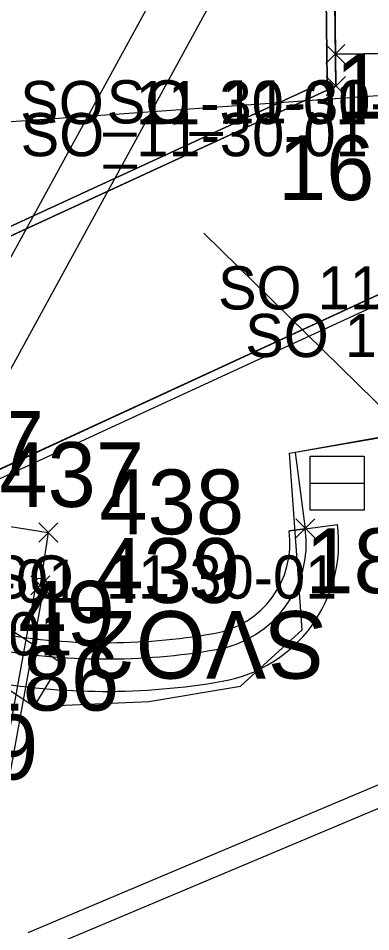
# Model space of a CAD drawing. Extents: x -728800 to -728100, y -1073200 to -1072700.
# Drawn here: x -728515.29 to -728512.03, y -1073056.81 to -1073048.35 of the extents above; entities that cross this region are included whole.
import ezdxf

# ---------------------------------------------------------------- set-up
doc = ezdxf.new("R2010")
doc.units = 0
for name, color, linetype in [('_NOR-návrh tenká', 7, 'Continuous'), ('_NOR-šraf_+-0', 7, 'Continuous'), ('_NOR-šraf_+12', 7, 'Continuous'), ('_NOR-šraf_+6', 7, 'Continuous'), ('_NOR-šraf_chodník', 7, 'Continuous'), ('_NOR-šraf_signální pás', 7, 'Continuous'), ('_NOR-šraf_vozovka', 7, 'Continuous'), ('_NOR-šraf_zeleň', 7, 'Continuous'), ('A2_OBVOD STAVBY', 7, 'Continuous'), ('B1_body_poloha', 7, 'Continuous'), ('B2_body_číslo', 7, 'Continuous'), ('B3_body_popiska', 7, 'Continuous'), ('B4_Bodové pole', 7, 'Continuous'), ('B6_JŽM', 7, 'Continuous'), ('KOS_kabelová trasa VO', 7, 'Continuous'), ('KOS_nové prvky VO', 7, 'Continuous'), ('KTA_členění PS a SO', 7, 'Continuous'), ('ZA_02_Dočasný_do_1_roku', 7, 'Continuous')]:
    doc.layers.add(name, color=color, linetype=linetype)

msp = doc.modelspace()

# ---------------------------------------------------------------- linework, layer by layer
at = {"layer": '_NOR-návrh tenká'}
msp.add_line((-728511.5598, -1073048.6726), (-728512.3598, -1073048.6815), dxfattribs=at)
for points in [[(-728512.437, -1073048.9275), (-728512.4624, -1073046.6351)], [(-728512.3565, -1073048.9785), (-728512.3823, -1073046.6472)], [(-728516.9231, -1073050.9957), (-728512.437, -1073048.9275)], [(-728516.8896, -1073051.0683), (-728512.3565, -1073048.9785)], [(-728516.0858, -1073052.812), (-728510.6464, -1073050.3043)], [(-728516.0523, -1073052.8846), (-728510.6571, -1073050.3973)], [(-728512.6386, -1073053.0791), (-728512.3411, -1073053.0398)], [(-728512.6386, -1073053.0791), (-728512.7873, -1073053.0987)], [(-728512.6386, -1073053.0791), (-728512.6386, -1073053.0791)]]:
    msp.add_lwpolyline(points, dxfattribs=at)
for centre, radius, start, end in [((-728513.6299, -1073053.2101), 1.3, 279.85546, 7.52816), ((-728513.6299, -1073053.2101), 0.85, 279.85546, 7.52816), ((-728513.6299, -1073053.2101), 1, 279.85546, 7.52816), ((-728514.4858, -1073048.2839), 5.85, 259.67159, 279.85546), ((-728514.4858, -1073048.2839), 6, 259.67159, 279.85546), ((-728514.4858, -1073048.2839), 6.3, 259.67159, 279.85546)]:
    msp.add_arc(centre, radius, start, end, dxfattribs=at)
at = {"layer": '_NOR-šraf_+-0'}
msp.add_lwpolyline([(-728516.0523, -1073052.8846), (-728510.6571, -1073050.3973), (-728510.6464, -1073050.3043), (-728516.0858, -1073052.812)], dxfattribs=at)
at = {"layer": '_NOR-šraf_+12'}
msp.add_lwpolyline([(-728512.7873, -1073053.0987), (-728512.6386, -1073053.0791)], dxfattribs=at)
for centre, radius, start, end in [((-728513.6299, -1073053.2101), 0.85, 279.85546, 7.52816), ((-728513.6299, -1073053.2101), 1, 279.85546, 7.52816), ((-728514.4858, -1073048.2839), 5.85, 259.67159, 279.85546), ((-728514.4858, -1073048.2839), 6, 259.67159, 279.85546)]:
    msp.add_arc(centre, radius, start, end, dxfattribs=at)
at = {"layer": '_NOR-šraf_+6'}
for points in [[(-728516.9231, -1073050.9957), (-728512.437, -1073048.9275), (-728512.4624, -1073046.6351)], [(-728512.4624, -1073046.6351), (-728512.3823, -1073046.6472), (-728512.3823, -1073046.6472), (-728512.3778, -1073047.0523), (-728512.3598, -1073048.6815), (-728512.3565, -1073048.9785), (-728516.7519, -1073051.0049), (-728516.8896, -1073051.0683)]]:
    msp.add_lwpolyline(points, dxfattribs=at)
at = {"layer": '_NOR-šraf_chodník'}
for p, q in [((-728512.3598, -1073048.6815), (-728511.5598, -1073048.6726)), ((-728512.3565, -1073048.9785), (-728512.3598, -1073048.6815)), ((-728516.7519, -1073051.0049), (-728512.3565, -1073048.9785)), ((-728510.6464, -1073050.3043), (-728516.0858, -1073052.812))]:
    msp.add_line(p, q, dxfattribs=at)
at = {"layer": '_NOR-šraf_signální pás'}
msp.add_lwpolyline([(-728512.3598, -1073048.6815), (-728511.5598, -1073048.6726), (-728511.5764, -1073047.1727), (-728512.3778, -1073047.0523), (-728512.3598, -1073048.6815)], dxfattribs=at)
at = {"layer": '_NOR-šraf_vozovka'}
msp.add_lwpolyline([(-728512.6386, -1073053.0791), (-728512.3411, -1073053.0398)], dxfattribs=at)
for centre, radius, start, end in [((-728513.6299, -1073053.2101), 1.3, 279.85546, 7.52816), ((-728513.6299, -1073053.2101), 1, 279.85546, 7.52816), ((-728514.4858, -1073048.2839), 6, 259.67159, 279.85546), ((-728514.4858, -1073048.2839), 6.3, 259.67159, 279.85546)]:
    msp.add_arc(centre, radius, start, end, dxfattribs=at)
at = {"layer": '_NOR-šraf_zeleň'}
for points in [[(-728515.0597, -1073046.2449), (-728512.4624, -1073046.6351), (-728512.437, -1073048.9275), (-728516.9231, -1073050.9957)], [(-728516.0523, -1073052.8846), (-728510.6571, -1073050.3973), (-728510.7036, -1073050.8035), (-728510.5546, -1073050.8206), (-728510.651, -1073051.661), (-728511.32, -1073052.432), (-728511.438, -1073052.141), (-728512.732, -1073052.372), (-728512.6386, -1073053.0791), (-728512.7873, -1073053.0987)]]:
    msp.add_lwpolyline(points, dxfattribs=at)
for centre, radius, start, end in [((-728513.6299, -1073053.2101), 0.85, 279.85546, 7.52816), ((-728514.4858, -1073048.2839), 5.85, 259.67159, 279.85546)]:
    msp.add_arc(centre, radius, start, end, dxfattribs=at)
at = {"layer": 'A2_OBVOD STAVBY'}
msp.add_lwpolyline([(-728515.0412, -1073056.9667), (-728511.7977, -1073055.5968), (-728511.0404, -1073055.2769), (-728508.4004, -1073049.5903), (-728508.3173, -1073048.8652)], dxfattribs=at)
at = {"layer": 'B1_body_poloha'}
for p, q in [((-728512.4484, -1073048.5926), (-728512.2716, -1073048.7694)), ((-728512.4484, -1073048.7694), (-728512.2716, -1073048.5926)), ((-728512.4444, -1073048.8896), (-728512.2676, -1073049.0664)), ((-728512.4444, -1073049.0664), (-728512.2676, -1073048.8896)), ((-728515.1044, -1073053.0246), (-728514.9276, -1073053.2014)), ((-728515.1044, -1073053.2014), (-728514.9276, -1073053.0246)), ((-728512.7264, -1073052.9866), (-728512.5496, -1073053.1634)), ((-728512.7264, -1073053.1634), (-728512.5496, -1073052.9866)), ((-728515.1784, -1073053.5126), (-728515.0016, -1073053.6894)), ((-728515.1784, -1073053.6894), (-728515.0016, -1073053.5126))]:
    msp.add_line(p, q, dxfattribs=at)
at = {"layer": 'B2_body_číslo'}
for p, q in [((-728512.36, -1073048.681), (-728512.36, -1073048.681)), ((-728512.356, -1073048.978), (-728512.356, -1073048.978)), ((-728515.016, -1073053.113), (-728515.016, -1073053.113)), ((-728512.638, -1073053.075), (-728512.638, -1073053.075)), ((-728515.09, -1073053.601), (-728515.09, -1073053.601))]:
    msp.add_line(p, q, dxfattribs=at)
at = {"layer": 'B4_Bodové pole'}
msp.add_line((-728502.086, -1073048.369), (-728521.333, -1073049.732), dxfattribs=at)
at = {"layer": 'B6_JŽM'}
for points in [[(-728515.148, -1073054.725), (-728514.9, -1073054.321), (-728516.336, -1073053.379), (-728512.168, -1073045.742), (-728510.38, -1073046.047), (-728509.916, -1073045.565), (-728514.343, -1073044.959), (-728514.586, -1073045.376), (-728512.695, -1073045.676), (-728516.744, -1073053.086), (-728518.227, -1073052.067), (-728518.483, -1073052.487), (-728515.148, -1073054.725)], [(-728515.148, -1073054.725), (-728514.0859, -1073054.6787), (-728513.2393, -1073054.5358), (-728512.667, -1073054.014), (-728512.785, -1073052.379), (-728511.438, -1073052.146), (-728511.426, -1073052.561), (-728510.655, -1073051.729), (-728509.916, -1073045.565)], [(-728512.594, -1073052.656), (-728512.594, -1073052.406), (-728512.094, -1073052.406), (-728512.094, -1073052.906), (-728512.594, -1073052.906), (-728512.594, -1073052.656), (-728512.094, -1073052.656)]]:
    msp.add_lwpolyline(points, dxfattribs=at)
at = {"layer": 'KOS_kabelová trasa VO'}
msp.add_lwpolyline([(-728528.7388, -1073080.1922), (-728527.3958, -1073080.5542), (-728522.1845, -1073062.5559), (-728521.7095, -1073061.3747), (-728517.3063, -1073062.1713), (-728515.6394, -1073053.0154), (-728515.0161, -1073053.1134), (-728515.0904, -1073053.6006)], dxfattribs=at)
at = {"layer": 'KOS_nové prvky VO'}
for p, q in [((-728515.576, -1073056.0533), (-728515.1376, -1073053.6475)), ((-728515.5012, -1073056.0669), (-728515.0628, -1073053.6611))]:
    msp.add_line(p, q, dxfattribs=at)
msp.add_circle((-728515.0904, -1073053.6006), 0.0665, dxfattribs=at)
at = {"layer": 'KTA_členění PS a SO'}
msp.add_line((-728508.9378, -1073054.8998), (-728513.577, -1073050.3407), dxfattribs=at)
at = {"layer": 'ZA_02_Dočasný_do_1_roku'}
msp.add_lwpolyline([(-728515.2033, -1073056.8181), (-728511.1894, -1073055.1227), (-728508.5954, -1073049.5354), (-728508.4924, -1073048.6368), (-728517.3822, -1073047.3107), (-728520.487, -1073049.0255), (-728522.1871, -1073049.6168), (-728521.173, -1073052.5328), (-728520.1133, -1073054.1527), (-728521.5861, -1073059.3376)], dxfattribs=at)

# ---------------------------------------------------------------- texts
at = {"layer": 'B2_body_číslo'}
for s, p in [('168', (-728512.36, -1073049.281)), ('169', (-728512.8919, -1073050.0338)), ('177', (-728516.3946, -1073052.5864)), ('437', (-728515.4692, -1073052.8761)), ('438', (-728514.5434, -1073053.1292)), ('187', (-728512.638, -1073053.675)), ('439', (-728514.5805, -1073053.765)), ('449', (-728515.739, -1073054.161)), ('186', (-728515.699, -1073054.762)), ('259', (-728516.4475, -1073055.4004))]:
    msp.add_text(s, height=0.6, dxfattribs=at).set_placement(p)
at = {"layer": 'B3_body_popiska'}
for s, p in [('SO_11-30-01', (-728515.2759, -1073049.331)), ('SO_11-30-01', (-728514.4749, -1073049.324)), ('SO_11-30-01', (-728515.2719, -1073049.628)), ('SO 11-30-01', (-728513.4457, -1073051.047)), ('SO 11-30-01', (-728513.1947, -1073051.488)), ('SO_11-53-01', (-728517.9319, -1073053.763)), ('SO_11-30-01', (-728515.5539, -1073053.725)), ('SO_11-53-01', (-728518.0059, -1073054.251))]:
    msp.add_text(s, height=0.4, dxfattribs=at).set_placement(p)
at = {"layer": 'KOS_nové prvky VO'}
msp.add_text('SVO2', height=0.625, rotation=180, dxfattribs=at).set_placement((-728512.4431, -1073053.8404))

doc.saveas('drawing.dxf')
